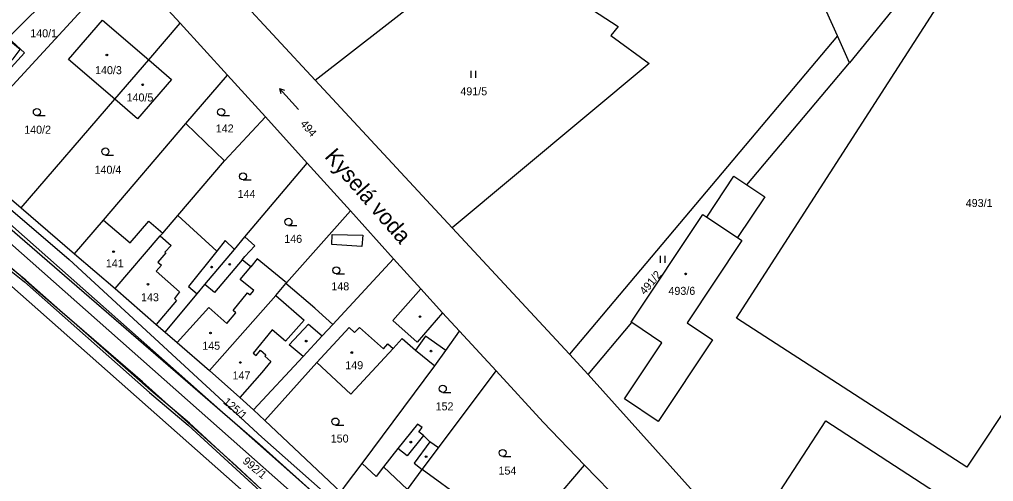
# Model space of a CAD drawing. Extents: x -757266 to -753360, y -1162585 to -1157740.
# Drawn here: x -754934.7 to -754727.9, y -1161798.3 to -1161700.2 of the extents above; entities that cross this region are included whole.
import ezdxf

# ---------------------------------------------------------------- set-up
doc = ezdxf.new("R2010")
doc.units = 0
for name, color, linetype in [('Hranice parcel', 7, 'Continuous'), ('Parcelní čísla', 7, 'Continuous'), ('Pop  PČ popisy', 7, 'Continuous'), ('Vnitřní kresba', 7, 'Continuous'), ('Věcná břemena k části', 7, 'Continuous'), ('Značky budov', 7, 'Continuous'), ('Značky kultur', 7, 'Continuous')]:
    doc.layers.add(name, color=color, linetype=linetype)

msp = doc.modelspace()

# ---------------------------------------------------------------- linework, layer by layer
at = {"layer": 'Hranice parcel'}
for p, q in [((-754871.95, -1161713.02), (-754913.71, -1161667.99)), ((-754871.95, -1161713.02), (-754834.66, -1161683.96)), ((-754834.66, -1161683.96), (-754807.62, -1161701.64)), ((-754948.77, -1161727.83), (-754912.31, -1161688.18)), ((-754900.61, -1161700.97), (-754912.31, -1161688.18)), ((-754761.02, -1161703.65), (-754766.3, -1161691.75)), ((-754748.55, -1161697.18), (-754758.49, -1161709.34)), ((-754907.29, -1161708.74), (-754900.61, -1161700.97)), ((-754890.53, -1161711.98), (-754900.61, -1161700.97)), ((-754761.02, -1161703.65), (-754817.93, -1161771.28)), ((-754758.49, -1161709.34), (-754761.02, -1161703.65)), ((-754914.5, -1161717.12), (-754907.29, -1161708.74)), ((-754780.24, -1161735.32), (-754758.49, -1161709.34)), ((-754899.44, -1161722.28), (-754890.53, -1161711.98)), ((-754882.46, -1161720.82), (-754890.53, -1161711.98)), ((-754842.82, -1161744.44), (-754871.95, -1161713.02)), ((-754934.36, -1161740.2), (-754914.5, -1161717.12)), ((-754891.18, -1161730.2), (-754899.44, -1161722.28)), ((-754891.18, -1161730.2), (-754882.46, -1161720.82)), ((-754873.65, -1161730.71), (-754882.46, -1161720.82)), ((-754948.77, -1161727.83), (-754934.36, -1161740.2)), ((-754901.13, -1161741.83), (-754891.18, -1161730.2)), ((-754886.86, -1161746.34), (-754873.65, -1161730.71)), ((-754864.46, -1161740.82), (-754873.65, -1161730.71)), ((-754934.36, -1161740.2), (-754923.04, -1161749.93)), ((-754878.05, -1161756.11), (-754864.46, -1161740.82)), ((-754855.27, -1161750.98), (-754864.46, -1161740.82)), ((-754817.93, -1161771.28), (-754842.82, -1161744.44)), ((-754889.1, -1161749.01), (-754886.86, -1161746.34)), ((-754923.04, -1161749.93), (-754914.4, -1161757.3)), ((-754868.2, -1161764.97), (-754855.27, -1161750.98)), ((-754878.16, -1161756.23), (-754878.05, -1161756.11)), ((-754813.94, -1161775.57), (-754804.72, -1161764.56)), ((-754833.48, -1161774.78), (-754841.27, -1161766.4)), ((-754817.93, -1161771.28), (-754813.94, -1161775.57)), ((-754861.99, -1161794.51), (-754846.5, -1161773.77)), ((-754845.76, -1161791.14), (-754833.48, -1161774.78)), ((-754885, -1161783.11), (-754882.65, -1161785.33)), ((-754882.65, -1161785.33), (-754866.5, -1161800.56)), ((-754849.21, -1161795.73), (-754845.76, -1161791.14)), ((-754829.3, -1161811.83), (-754814.71, -1161794.87)), ((-754806.13, -1161803.63), (-754814.71, -1161794.87))]:
    msp.add_line(p, q, dxfattribs=at)
for points in [[(-755004.34, -1161674.23), (-754991.87, -1161692.75), (-754961.05, -1161719.56), (-754924.16, -1161751.14), (-754883.24, -1161788.9), (-754859.67, -1161809.81)], [(-754952.34, -1161724.76), (-754945.68, -1161717.94), (-754941, -1161713.33), (-754936.08, -1161708.51), (-754934.57, -1161706.55), (-754937.36, -1161704.29), (-754937.15, -1161704.08), (-754916.55, -1161683.55)], [(-754914.5, -1161717.12), (-754924.29, -1161708.7), (-754917.11, -1161700.29), (-754907.29, -1161708.74)], [(-754807.62, -1161701.64), (-754809.17, -1161703.58), (-754801, -1161709.54), (-754842.82, -1161744.44)], [(-754907.29, -1161708.74), (-754902.46, -1161712.89), (-754909.68, -1161721.27), (-754914.5, -1161717.12)], [(-754923.04, -1161749.93), (-754916.92, -1161742.76), (-754899.44, -1161722.28)], [(-754804.72, -1161764.56), (-754804.85, -1161764.48), (-754789.63, -1161741.62), (-754788.78, -1161742.18), (-754783.01, -1161733.47), (-754780.24, -1161735.32)], [(-754780.24, -1161735.32), (-754776.44, -1161737.85), (-754782.27, -1161746.49), (-754781.33, -1161747.11), (-754792.96, -1161764.6), (-754787.53, -1161768.2), (-754799.07, -1161785.58), (-754806.27, -1161780.78), (-754798.32, -1161768.84), (-754804.72, -1161764.56)], [(-754790.69, -1161920.17), (-754823.33, -1161865.1), (-754831.37, -1161854.01), (-754842.43, -1161841.79), (-754855.01, -1161828.87), (-754953.69, -1161741.58)], [(-754914.4, -1161757.3), (-754904.83, -1161746.15), (-754904.31, -1161745.54), (-754901.13, -1161741.83)], [(-754889.1, -1161749.01), (-754891.04, -1161747.13), (-754892.85, -1161749.38), (-754901.13, -1161741.83)], [(-754878.05, -1161756.11), (-754884.25, -1161750.98), (-754885.63, -1161752.68), (-754887.42, -1161751.2), (-754886.86, -1161750.54), (-754884.77, -1161748.25), (-754886.86, -1161746.34)], [(-754903.79, -1161766.62), (-754897.02, -1161758.47), (-754895.36, -1161756.49), (-754889.1, -1161749.01)], [(-754841.27, -1161766.4), (-754844.87, -1161762.45), (-754849.48, -1161757.4), (-754855.27, -1161750.98)], [(-754914.4, -1161757.3), (-754905.7, -1161764.94), (-754903.79, -1161766.62)], [(-754894.38, -1161774.75), (-754880.31, -1161758.79), (-754878.16, -1161756.23)], [(-754868.2, -1161764.97), (-754871.19, -1161762.26), (-754872.01, -1161761.48), (-754878.16, -1161756.23)], [(-754885, -1161783.11), (-754874.49, -1161771.77), (-754870.43, -1161767.39), (-754868.2, -1161764.97)], [(-754903.79, -1161766.62), (-754901.28, -1161768.76), (-754894.38, -1161774.75)], [(-754882.65, -1161785.33), (-754871.6, -1161773.02), (-754864.38, -1161779.75), (-754855.38, -1161770.09), (-754853.46, -1161767.96), (-754850.61, -1161770.4), (-754846.5, -1161773.77)], [(-754846.5, -1161773.77), (-754844.18, -1161770.49), (-754841.27, -1161766.4)], [(-754894.38, -1161774.75), (-754887.95, -1161780.48), (-754885, -1161783.11)], [(-754814.71, -1161794.87), (-754823.5, -1161785.69), (-754833.48, -1161774.78)], [(-754728.5, -1161864.92), (-754738.21, -1161858.31), (-754756.21, -1161838.63), (-754776.63, -1161817.12), (-754813.94, -1161775.57)], [(-754845.76, -1161791.14), (-754847.59, -1161789.9), (-754848.96, -1161788.52), (-754849.95, -1161787.73), (-754849.24, -1161786.86), (-754850.23, -1161786.13), (-754854.38, -1161791.33), (-754857.45, -1161795.19), (-754858.98, -1161797.27), (-754861.99, -1161794.51)], [(-754763.46, -1161785.44), (-754724.19, -1161811.01), (-754725.85, -1161813.54), (-754719.1, -1161817.94), (-754730.68, -1161835.75), (-754743.45, -1161827.41), (-754744.92, -1161829.64), (-754778.14, -1161807.96), (-754763.46, -1161785.44)], [(-754866.5, -1161800.56), (-754865.48, -1161799.19), (-754861.99, -1161794.51)], [(-754858.25, -1161808.07), (-754852.33, -1161799.99), (-754849.21, -1161795.73)], [(-754844.55, -1161820.66), (-754840.54, -1161816.09), (-754840.72, -1161815.93), (-754835.01, -1161808.29), (-754840.05, -1161802.42), (-754849.21, -1161795.73)]]:
    msp.add_lwpolyline(points, dxfattribs=at)
at = {"layer": 'Vnitřní kresba'}
for p, q in [((-754782.49, -1161763.64), (-754728.32, -1161679.57)), ((-754933.64, -1161707.24), (-754937.15, -1161704.08)), ((-754940.01, -1161714.16), (-754933.64, -1161707.24)), ((-754679.82, -1161714.24), (-754733.53, -1161795.26)), ((-754931.36, -1161757.54), (-754960.25, -1161731.5)), ((-754943.25, -1161738.89), (-754926.26, -1161753.63)), ((-754916.92, -1161742.76), (-754911.23, -1161747.61)), ((-754911.23, -1161747.61), (-754907.28, -1161742.98)), ((-754907.28, -1161742.98), (-754904.31, -1161745.54)), ((-754788.78, -1161742.18), (-754782.27, -1161746.49)), ((-754904.83, -1161746.15), (-754902.55, -1161748.16)), ((-754868.42, -1161747.99), (-754868.3, -1161745.81)), ((-754868.3, -1161745.81), (-754861.81, -1161746.01)), ((-754861.81, -1161746.01), (-754862, -1161748.41)), ((-754902.55, -1161748.16), (-754903.86, -1161749.56)), ((-754903.86, -1161749.56), (-754903.65, -1161749.75)), ((-754892.85, -1161749.38), (-754898.87, -1161756.86)), ((-754862, -1161748.41), (-754868.42, -1161747.99)), ((-754903.65, -1161749.75), (-754905.34, -1161751.69)), ((-754905.34, -1161751.69), (-754904.59, -1161752.36)), ((-754887.42, -1161751.2), (-754893.29, -1161758.15)), ((-754926.26, -1161753.63), (-754883.79, -1161790.36)), ((-754904.59, -1161752.36), (-754905.74, -1161753.65)), ((-754905.74, -1161753.65), (-754900.72, -1161758.01)), ((-754887.85, -1161755.4), (-754885.63, -1161752.68)), ((-754884.97, -1161757.71), (-754887.85, -1161755.4)), ((-754908.58, -1161777.13), (-754931.36, -1161757.54)), ((-754898.87, -1161756.86), (-754897.02, -1161758.47)), ((-754893.29, -1161758.15), (-754895.36, -1161756.49)), ((-754885.74, -1161758.64), (-754884.97, -1161757.71)), ((-754855.45, -1161764.13), (-754849.48, -1161757.4)), ((-754901.36, -1161759.83), (-754905.7, -1161764.94)), ((-754900.72, -1161758.01), (-754901.83, -1161759.41)), ((-754901.83, -1161759.41), (-754901.36, -1161759.83)), ((-754889.37, -1161761.96), (-754886.28, -1161758.2)), ((-754886.28, -1161758.2), (-754885.74, -1161758.64)), ((-754880.31, -1161758.79), (-754874.27, -1161764.07)), ((-754901.28, -1161768.76), (-754894.51, -1161761.35)), ((-754894.51, -1161761.35), (-754890.67, -1161764.72)), ((-754888.78, -1161762.51), (-754889.37, -1161761.96)), ((-754890.67, -1161764.72), (-754888.78, -1161762.51)), ((-754874.27, -1161764.07), (-754878.21, -1161768.52)), ((-754850.27, -1161768.69), (-754855.45, -1161764.13)), ((-754844.87, -1161762.45), (-754850.27, -1161768.69)), ((-754733.53, -1161795.26), (-754782.49, -1161763.64)), ((-754881.06, -1161766.09), (-754885.13, -1161771.03)), ((-754878.21, -1161768.52), (-754881.06, -1161766.09)), ((-754877.44, -1161769.25), (-754873.32, -1161764.86)), ((-754873.32, -1161764.86), (-754870.43, -1161767.39)), ((-754871.6, -1161773.02), (-754864.69, -1161765.63)), ((-754864.69, -1161765.63), (-754863.57, -1161766.68)), ((-754863.57, -1161766.68), (-754862.5, -1161765.56)), ((-754862.5, -1161765.56), (-754857.43, -1161770.14)), ((-754848.51, -1161767.42), (-754850.61, -1161770.4)), ((-754844.18, -1161770.49), (-754848.51, -1161767.42)), ((-754874.49, -1161771.77), (-754877.44, -1161769.25)), ((-754857.43, -1161770.14), (-754856.47, -1161769.09)), ((-754856.47, -1161769.09), (-754855.38, -1161770.09)), ((-754885.13, -1161771.03), (-754884.48, -1161771.51)), ((-754884.48, -1161771.51), (-754883.53, -1161770.42)), ((-754883.53, -1161770.42), (-754882.41, -1161771.4)), ((-754882.41, -1161771.4), (-754882.64, -1161771.67)), ((-754882.64, -1161771.67), (-754881.34, -1161772.8)), ((-754881.34, -1161772.8), (-754883.28, -1161775.18)), ((-754883.28, -1161775.18), (-754887.95, -1161780.48)), ((-754888.68, -1161795.04), (-754908.58, -1161777.13)), ((-754848.96, -1161788.52), (-754852.42, -1161792.85)), ((-754883.79, -1161790.36), (-754860.97, -1161810.87)), ((-754847.59, -1161789.9), (-754850.91, -1161794.38)), ((-754852.42, -1161792.85), (-754854.38, -1161791.33)), ((-754865.57, -1161816.45), (-754888.68, -1161795.04)), ((-754850.91, -1161794.38), (-754849.21, -1161795.73)), ((-754857.45, -1161795.19), (-754852.33, -1161799.99))]:
    msp.add_line(p, q, dxfattribs=at)
at = {"layer": 'Věcná břemena k části'}
for points in [[(-755000.56, -1161691.1), (-754866.29, -1161810.04), (-754834.82, -1161839.85), (-754788.28, -1161915.03), (-754787.47, -1161923.67), (-754787.16, -1161925.55), (-754783.07, -1161931.76), (-754784.49, -1161923.29), (-754785.36, -1161914.05), (-754832.48, -1161837.94), (-754864.27, -1161807.82), (-754998.15, -1161689.22)], [(-754939.4, -1161751.33), (-754933.69, -1161755.9), (-754907.13, -1161779.39), (-754898.93, -1161786.31), (-754886.19, -1161798.05), (-754866.21, -1161816.39)], [(-754865.87, -1161816.03), (-754885.85, -1161797.69), (-754898.61, -1161785.93), (-754906.81, -1161779.01), (-754933.37, -1161755.51), (-754939.19, -1161750.85)]]:
    msp.add_lwpolyline(points, dxfattribs=at)
at = {"layer": 'Značky budov'}
for centre in [(-754916.1668, -1161707.7092), (-754908.5668, -1161714.0392), (-754914.7568, -1161749.4892), (-754893.9368, -1161752.7692), (-754890.0868, -1161752.1692), (-754793.2568, -1161754.2092), (-754907.4568, -1161756.3992), (-754849.6668, -1161763.2792), (-754894.1668, -1161766.7492), (-754873.8368, -1161768.4892), (-754864.1668, -1161770.9092), (-754847.3268, -1161770.6092), (-754887.8168, -1161773.0292), (-754851.6268, -1161789.9492), (-754848.3768, -1161793.0492)]:
    msp.add_circle(centre, 0.175, dxfattribs=at)
at = {"layer": 'Značky kultur'}
for p, q in [((-754838.791, -1161712.58), (-754838.791, -1161711.08)), ((-754837.79, -1161712.58), (-754837.79, -1161711.08)), ((-754875.478, -1161719.271), (-754879.492, -1161714.812)), ((-754879.492, -1161714.812), (-754879.211, -1161715.874)), ((-754879.492, -1161714.812), (-754878.466, -1161715.203)), ((-754931.033, -1161720.59), (-754929.283, -1161720.59)), ((-754891.903, -1161720.59), (-754890.153, -1161720.59)), ((-754916.493, -1161728.96), (-754914.743, -1161728.96)), ((-754887.263, -1161734.24), (-754885.513, -1161734.24)), ((-754877.613, -1161743.9), (-754875.863, -1161743.9)), ((-754798.611, -1161751.85), (-754798.611, -1161750.35)), ((-754797.61, -1161751.85), (-754797.61, -1161750.35)), ((-754867.443, -1161754.2), (-754865.693, -1161754.2)), ((-754844.843, -1161779.37), (-754843.093, -1161779.37)), ((-754867.633, -1161786.33), (-754865.883, -1161786.33)), ((-754832.103, -1161792.99), (-754830.353, -1161792.99))]:
    msp.add_line(p, q, dxfattribs=at)
for centre in [(-754931.0329, -1161719.8398), (-754891.9029, -1161719.8398), (-754916.4929, -1161728.2098), (-754887.2629, -1161733.4898), (-754877.6129, -1161743.1498), (-754867.4429, -1161753.4498), (-754844.8429, -1161778.6198), (-754867.6329, -1161785.5798), (-754832.1029, -1161792.2398)]:
    msp.add_circle(centre, 0.75, dxfattribs=at)

# ---------------------------------------------------------------- texts
at = {"layer": 'Parcelní čísla'}
for s, p in [('140/1', (-754932.44, -1161703.95)), ('140/3', (-754918.68, -1161711.78)), ('491/5', (-754841.1, -1161716.27)), ('140/5', (-754911.99, -1161717.58)), ('140/2', (-754933.73, -1161724.43)), ('142', (-754893.05, -1161724.17)), ('140/4', (-754918.79, -1161732.93)), ('144', (-754888.41, -1161738.08)), ('493/1', (-754733.77, -1161740)), ('146', (-754878.5, -1161747.61)), ('141', (-754916.39, -1161752.81)), ('148', (-754868.5, -1161757.7)), ('493/6', (-754796.908, -1161758.66)), ('143', (-754908.92, -1161760.02)), ('145', (-754895.92, -1161770.32)), ('149', (-754865.54, -1161774.45)), ('147', (-754889.49, -1161776.63)), ('152', (-754846.36, -1161783.2)), ('150', (-754868.63, -1161790.03)), ('154', (-754833, -1161796.84))]:
    msp.add_text(s, height=1.7, dxfattribs=at).set_placement(p)
for s, rotation, p in [('494', 311, (-754875.221, -1161722.397)), ('491/2', 50, (-754801.908, -1161758.776)), ('125/1', 319, (-754891.617, -1161781.591)), ('992/1', 320, (-754887.486, -1161794.231))]:
    msp.add_text(s, height=1.7, rotation=rotation, dxfattribs=at).set_placement(p)
at = {"layer": 'Pop  PČ popisy'}
msp.add_text('Kyselá voda', height=3.399996, rotation=311, dxfattribs=at).set_placement((-754870.093, -1161729.385))

doc.saveas('drawing.dxf')
